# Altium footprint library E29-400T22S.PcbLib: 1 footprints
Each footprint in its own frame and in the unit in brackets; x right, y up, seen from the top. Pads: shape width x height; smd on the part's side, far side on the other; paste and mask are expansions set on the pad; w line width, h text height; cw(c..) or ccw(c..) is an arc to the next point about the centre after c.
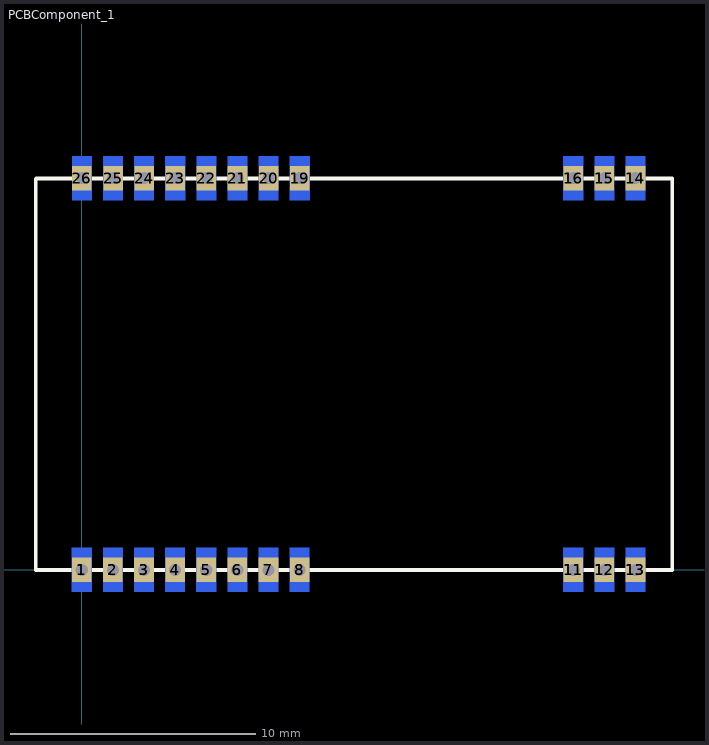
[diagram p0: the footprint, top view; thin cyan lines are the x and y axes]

## PCBComponent_1 [mm]
pads (44):
  rect 0.8x1 hole 0.5: 1(0,0) 2(1.27,0) 3(2.54,0) 4(3.81,0) 5(5.08,0) 6(6.35,0) 7(7.62,0) 8(8.89,0) 11(20.064,0) 12(21.334,0) 13(22.604,0) 14(22.604,15.997) 15(21.334,15.997) 16(20.064,15.997) 19(8.896,15.997) 20(7.626,15.997) 21(6.356,15.997) 22(5.086,15.997) 23(3.816,15.997) 24(2.546,15.997) 25(1.276,15.997) 26(0.006,15.997)
  rect 0.8x1.8 smd far side: 1(0,0) 2(1.27,0) 3(2.54,0) 4(3.81,0) 5(5.08,0) 6(6.35,0) 7(7.62,0) 8(8.89,0) 11(20.064,0) 12(21.334,0) 13(22.604,0) 14(22.604,15.997) 15(21.334,15.997) 16(20.064,15.997) 19(8.896,15.997) 20(7.626,15.997) 21(6.356,15.997) 22(5.086,15.997) 23(3.816,15.997) 24(2.546,15.997) 25(1.276,15.997) 26(0.006,15.997)
Top Overlay:
  lines w0.152: -1.877,15.957 -1.877,0 24.08,0 24.102,0 24.102,15.979 -1.856,15.979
